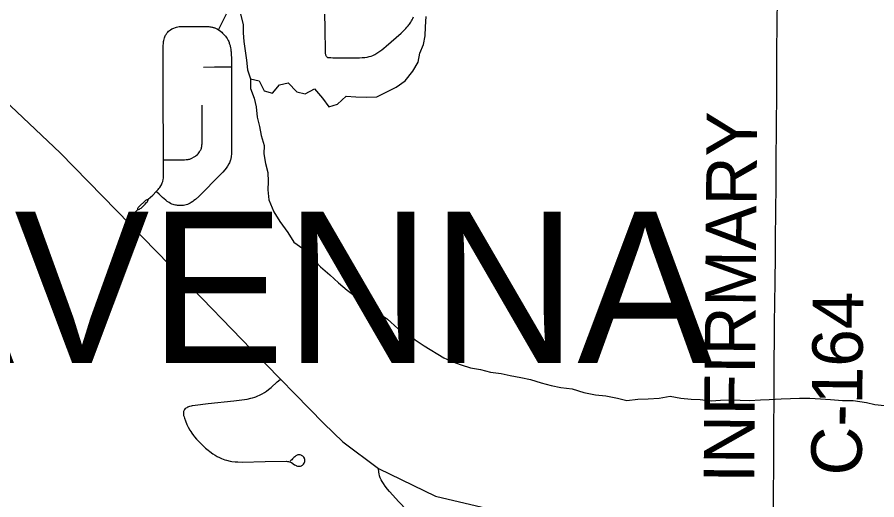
# Model space of a CAD drawing. Extents: x 0 to 34, y 0 to 22.
# Drawn here: x 6.114 to 7.081, y 15.953 to 16.497 of the extents above; entities that cross this region are included whole.
import ezdxf

# ---------------------------------------------------------------- set-up
doc = ezdxf.new("R2010")
doc.units = 0
for name, color, linetype in [('GM_X_County_Road', 7, 'Continuous'), ('GM_X_County_Road_Text', 7, 'Continuous'), ('GM_X_Minor_River', 7, 'Continuous'), ('GM_X_Township_Road', 7, 'Continuous'), ('GM_X_Township_Text', 7, 'Continuous'), ('SH_Text', 7, 'Continuous')]:
    doc.layers.add(name, color=color, linetype=linetype)

msp = doc.modelspace()

# ---------------------------------------------------------------- linework, layer by layer
at = {"layer": 'GM_X_County_Road'}
for points in [[(6.96457, 15.94259), (6.96493, 16.00864), (6.96526, 16.09208), (6.96585, 16.15178), (6.96662, 16.19817), (6.96685, 16.22811), (6.96676, 16.24735), (6.96754, 16.30754), (6.96784, 16.32982), (6.96821, 16.3767), (6.96833, 16.40802), (6.96848, 16.45844), (6.96872, 16.4883), (6.96914, 16.51872)], [(6.61999, 15.87248), (6.60999, 15.88265), (6.59119, 15.90161), (6.57606, 15.91717), (6.56178, 15.93189), (6.54315, 15.95108), (6.5327, 15.96251), (6.53052, 15.96512), (6.52794, 15.9685), (6.52592, 15.97148), (6.52447, 15.97373), (6.5233, 15.97579), (6.5223, 15.97804), (6.52149, 15.9804), (6.521, 15.98243), (6.52067, 15.98451), (6.52045, 15.98844)]]:
    msp.add_lwpolyline(points, dxfattribs=at)
at = {"layer": 'GM_X_Minor_River'}
for points in [[(6.36528, 16.49984), (6.36802, 16.48849), (6.3681, 16.47901), (6.36893, 16.46916), (6.37053, 16.45856), (6.37175, 16.44833), (6.37297, 16.43734), (6.37646, 16.42713), (6.37655, 16.41614), (6.38042, 16.40555), (6.38276, 16.39571), (6.38399, 16.38397), (6.38635, 16.37337), (6.38832, 16.36353), (6.39182, 16.35218), (6.39151, 16.3427), (6.39311, 16.33172), (6.39584, 16.32188), (6.3963, 16.31165), (6.396, 16.30217), (6.39685, 16.2908), (6.40263, 16.27757), (6.40953, 16.26663), (6.41833, 16.25419), (6.42523, 16.24325), (6.43513, 16.23612), (6.44467, 16.22671), (6.45497, 16.21542), (6.46564, 16.2064), (6.47556, 16.19738), (6.48508, 16.18911), (6.49689, 16.18048), (6.50754, 16.17298), (6.51897, 16.16434), (6.53038, 16.15647), (6.5422, 16.14632), (6.55169, 16.14185)], [(6.37646, 16.42713), (6.38632, 16.42494), (6.39171, 16.4136), (6.40119, 16.41102), (6.40906, 16.42056), (6.41889, 16.42253), (6.42843, 16.41237), (6.43791, 16.41016), (6.44846, 16.41593), (6.45725, 16.40538), (6.46452, 16.39558), (6.47433, 16.39869), (6.4841, 16.40749), (6.49471, 16.40681), (6.50644, 16.40652), (6.51855, 16.40699), (6.52911, 16.412), (6.54042, 16.41777), (6.5502, 16.42505), (6.55882, 16.43574), (6.56517, 16.44602), (6.56698, 16.45589), (6.57107, 16.46578), (6.57288, 16.47565), (6.57318, 16.48589), (6.57384, 16.49727)], [(6.55169, 16.14185), (6.5616, 16.1332), (6.57188, 16.12646), (6.59393, 16.11298), (6.60381, 16.1085), (6.6133, 16.10516), (6.62392, 16.10183), (6.63529, 16.10002), (6.64629, 16.09708), (6.65841, 16.09565), (6.66865, 16.09308), (6.6804, 16.09089), (6.6914, 16.0887), (6.70354, 16.085), (6.71454, 16.08206), (6.72553, 16.07986), (6.73804, 16.07806), (6.75131, 16.074), (6.76458, 16.07144), (6.77594, 16.07039), (6.78921, 16.06784), (6.79983, 16.06527), (6.81193, 16.0665), (6.82366, 16.06697), (6.83614, 16.06782), (6.84862, 16.06981), (6.86037, 16.06763), (6.87211, 16.06658), (6.88233, 16.06628), (6.89445, 16.06486), (6.90505, 16.06532), (6.9164, 16.06578), (6.92738, 16.06549), (6.9376, 16.06519), (6.95008, 16.06566), (6.95992, 16.06612), (6.97316, 16.06698), (6.98375, 16.06744), (6.99397, 16.06789), (7.00571, 16.06761), (7.01744, 16.06694), (7.0288, 16.06627), (7.04244, 16.06523), (7.05417, 16.06495), (7.06933, 16.06279), (7.07881, 16.06058), (7.08941, 16.05953)]]:
    msp.add_lwpolyline(points, dxfattribs=at)
at = {"layer": 'GM_X_Township_Road'}
for points in [[(6.3404, 16.48247), (6.34926, 16.50034)], [(6.46194, 16.45228), (6.46153, 16.4529), (6.46118, 16.45363), (6.46099, 16.45439), (6.46088, 16.4552), (6.46084, 16.45586), (6.46082, 16.45664), (6.46028, 16.48453), (6.46018, 16.5001)], [(6.46194, 16.45228), (6.46253, 16.45169), (6.46317, 16.45133), (6.46415, 16.45112), (6.46498, 16.45105), (6.46571, 16.45102), (6.46661, 16.451), (6.46891, 16.45098), (6.48159, 16.45095), (6.49903, 16.45098), (6.50193, 16.45112), (6.50516, 16.45136), (6.50766, 16.45171), (6.51002, 16.45222), (6.51209, 16.45287), (6.51398, 16.45359), (6.51609, 16.45458), (6.51846, 16.45594), (6.5209, 16.45756), (6.52401, 16.45985), (6.52633, 16.46175), (6.5289, 16.46393), (6.54598, 16.4787), (6.54858, 16.48114), (6.55113, 16.48371), (6.55244, 16.4852), (6.55378, 16.48684), (6.55456, 16.48783), (6.55523, 16.48875), (6.55595, 16.48981), (6.55678, 16.49108), (6.55757, 16.49233), (6.55824, 16.49346), (6.55914, 16.49521), (6.55992, 16.49695)], [(6.27868, 16.33595), (6.27854, 16.35987), (6.27831, 16.39346), (6.27823, 16.44757), (6.27824, 16.46239), (6.27831, 16.46513), (6.27839, 16.46652), (6.27845, 16.46771), (6.27861, 16.46903), (6.27882, 16.47037), (6.27917, 16.47198), (6.27958, 16.47332), (6.28007, 16.47462), (6.28089, 16.47631), (6.28137, 16.4771), (6.28188, 16.47785), (6.28229, 16.47844), (6.28289, 16.47919), (6.28345, 16.47984), (6.28429, 16.48066), (6.28523, 16.48148), (6.28652, 16.48244), (6.28794, 16.48327), (6.29021, 16.48437), (6.29198, 16.48505), (6.29325, 16.48543), (6.29448, 16.48568), (6.29617, 16.48591), (6.29746, 16.48603), (6.2993, 16.4861), (6.30053, 16.4861), (6.30351, 16.48614), (6.31083, 16.48626), (6.31918, 16.48624), (6.32435, 16.4862), (6.32724, 16.48611), (6.32939, 16.48598), (6.3305, 16.48586), (6.33175, 16.48569), (6.33277, 16.4855), (6.33349, 16.48532), (6.33432, 16.48509), (6.33518, 16.48484), (6.33583, 16.48463), (6.33645, 16.48441), (6.33786, 16.48384), (6.33894, 16.48333), (6.3404, 16.48247)], [(6.3404, 16.48247), (6.34123, 16.48192), (6.34283, 16.48069), (6.34402, 16.47968), (6.34509, 16.47872), (6.34619, 16.4776), (6.34685, 16.47688), (6.34772, 16.47586), (6.34819, 16.47528), (6.34911, 16.47403), (6.34999, 16.47268), (6.35092, 16.47112), (6.35136, 16.47024), (6.35186, 16.46912), (6.35223, 16.46817), (6.35259, 16.46723), (6.35293, 16.46625), (6.35338, 16.46467), (6.35358, 16.46383), (6.3539, 16.46225), (6.35416, 16.46073), (6.35426, 16.46002), (6.3544, 16.45878), (6.35451, 16.45748), (6.35471, 16.4543), (6.35486, 16.45082), (6.35495, 16.44753), (6.35508, 16.4407)], [(6.35508, 16.4407), (6.35513, 16.43043), (6.35509, 16.38575), (6.35519, 16.36524), (6.35521, 16.35608), (6.35513, 16.34868), (6.35505, 16.34487), (6.35499, 16.34308), (6.35492, 16.34193), (6.35479, 16.34048), (6.35456, 16.33869), (6.35437, 16.33778), (6.35413, 16.33673), (6.35389, 16.33583), (6.35353, 16.3347), (6.35274, 16.33267), (6.35221, 16.33159), (6.35056, 16.32877), (6.34896, 16.32647), (6.3476, 16.32473), (6.34519, 16.32201), (6.34304, 16.31973), (6.31823, 16.29488), (6.31458, 16.29153), (6.31284, 16.29007), (6.31141, 16.28901), (6.30977, 16.28789), (6.30858, 16.28718), (6.30702, 16.28639), (6.30554, 16.28579), (6.30414, 16.28536), (6.30119, 16.28466), (6.29883, 16.28448), (6.29694, 16.28448), (6.29577, 16.28457), (6.29433, 16.28474), (6.29303, 16.28492), (6.29217, 16.28507), (6.29061, 16.28541), (6.2895, 16.28573), (6.28797, 16.28626), (6.28652, 16.28692), (6.28478, 16.28786), (6.28274, 16.28922), (6.28103, 16.2905), (6.27736, 16.29369), (6.27351, 16.29728), (6.27079, 16.29982)], [(6.32343, 16.44031), (6.33597, 16.44056), (6.35095, 16.44067), (6.35508, 16.4407)], [(6.27868, 16.33595), (6.28343, 16.336), (6.30228, 16.33618), (6.30392, 16.33624), (6.30499, 16.33634), (6.30626, 16.3365), (6.30692, 16.33663), (6.30803, 16.3369), (6.3091, 16.33724), (6.31058, 16.33787), (6.31312, 16.33921), (6.31442, 16.34005), (6.31535, 16.34074), (6.31669, 16.3419), (6.31763, 16.34287), (6.31838, 16.34379), (6.31918, 16.34492), (6.31997, 16.34635), (6.32036, 16.34715), (6.32073, 16.34811), (6.32111, 16.34928), (6.32129, 16.34996), (6.32153, 16.35103), (6.32169, 16.35195), (6.32182, 16.35289), (6.32192, 16.35414), (6.32201, 16.35533), (6.32207, 16.35685), (6.3221, 16.35796), (6.32211, 16.35967), (6.32212, 16.36268), (6.32195, 16.37404), (6.32196, 16.39753)], [(6.27029, 16.30028), (6.27084, 16.30084), (6.27237, 16.3025), (6.2734, 16.30372), (6.27442, 16.30501), (6.27562, 16.3068), (6.27632, 16.30803), (6.27721, 16.31011), (6.27776, 16.31177), (6.27826, 16.31394), (6.27847, 16.31534), (6.27864, 16.31791), (6.27872, 16.32627), (6.27868, 16.33595)], [(6.2494, 16.2799), (6.25028, 16.28006), (6.25158, 16.28053), (6.25245, 16.28103), (6.25332, 16.28172), (6.25777, 16.28606), (6.25956, 16.28796), (6.26004, 16.28846), (6.26052, 16.28909), (6.261, 16.28999), (6.26121, 16.29086), (6.26125, 16.29156), (6.26636, 16.29638), (6.27029, 16.30028)], [(6.2494, 16.2799), (6.2495, 16.28057), (6.24965, 16.28118), (6.25014, 16.2822), (6.25069, 16.28294), (6.25821, 16.29034), (6.25878, 16.29078), (6.25933, 16.29111), (6.26011, 16.29141), (6.26125, 16.29156)], [(6.23691, 16.26745), (6.23928, 16.26982), (6.2494, 16.2799)], [(6.30173, 16.05407), (6.30249, 16.05512), (6.30328, 16.05597), (6.30404, 16.05666), (6.30503, 16.05735), (6.3058, 16.05778), (6.30636, 16.05807), (6.3071, 16.05838), (6.30833, 16.05875), (6.3102, 16.05923), (6.31125, 16.05945), (6.31401, 16.05986), (6.32862, 16.06157), (6.35765, 16.06472), (6.37257, 16.06675), (6.37662, 16.06755), (6.37883, 16.06809), (6.38112, 16.06882), (6.38252, 16.06936), (6.38464, 16.07025), (6.38669, 16.07117), (6.38942, 16.07262), (6.39208, 16.07422), (6.39431, 16.07572), (6.3967, 16.07754), (6.39951, 16.07988), (6.40636, 16.08592), (6.40969, 16.08885)], [(6.30173, 16.05407), (6.30142, 16.05341), (6.30113, 16.05261), (6.30091, 16.05156), (6.30086, 16.05039), (6.30099, 16.04909), (6.30119, 16.04817), (6.30161, 16.04673), (6.30209, 16.04524), (6.3033, 16.04209), (6.3049, 16.03822), (6.3063, 16.03523), (6.30811, 16.03188), (6.30922, 16.03011), (6.31051, 16.02819), (6.31232, 16.0257), (6.3134, 16.02431), (6.31581, 16.02149), (6.31765, 16.01954), (6.32335, 16.01391), (6.32595, 16.01149), (6.32871, 16.00907), (6.3307, 16.00751), (6.33422, 16.00502), (6.33669, 16.00346), (6.33873, 16.00223), (6.34135, 16.00091), (6.34377, 15.99985), (6.34752, 15.99849), (6.34954, 15.99787), (6.35359, 15.99693), (6.35552, 15.99658), (6.35909, 15.99613), (6.36205, 15.99592), (6.36685, 15.99584), (6.39303, 15.99635), (6.41676, 15.99665), (6.41798, 15.99658), (6.41932, 15.99643), (6.42042, 15.99617), (6.42147, 15.99577), (6.42252, 15.99517), (6.42603, 15.99272), (6.42687, 15.9922), (6.4276, 15.99179), (6.42823, 15.99153), (6.4291, 15.99125), (6.43012, 15.99105), (6.43074, 15.99099), (6.43189, 15.99106), (6.43255, 15.9912), (6.43373, 15.99159), (6.4343, 15.9919), (6.43499, 15.99239), (6.43563, 15.99297), (6.43603, 15.99348), (6.43672, 15.99456), (6.43704, 15.99531), (6.43735, 15.99638), (6.43748, 15.99722), (6.43748, 15.99801), (6.43743, 15.99881), (6.43722, 15.99965), (6.43697, 16.00029), (6.43645, 16.00117), (6.43572, 16.00198), (6.43517, 16.0025), (6.43456, 16.00295), (6.43392, 16.00333), (6.43324, 16.00359), (6.4322, 16.00386), (6.43153, 16.00394), (6.43055, 16.00395), (6.42965, 16.00377), (6.42879, 16.00344), (6.42813, 16.00313), (6.42752, 16.00277), (6.42685, 16.0023), (6.42627, 16.00183), (6.42526, 16.00088), (6.42379, 15.99942), (6.42291, 15.99846), (6.42185, 15.99745), (6.42095, 15.9967)]]:
    msp.add_lwpolyline(points, dxfattribs=at)
at = {"layer": 'SH_Text'}
msp.add_lwpolyline([(6.04363, 16.45614), (6.16219, 16.3439), (6.22585, 16.27897), (6.29975, 16.20287), (6.37745, 16.12252), (6.45878, 16.03908), (6.4804, 16.01858), (6.52045, 15.98844), (6.58451, 15.95751), (6.64988, 15.94219), (6.71462, 15.93934), (6.79663, 15.94028), (7.82198, 15.947)], dxfattribs=at)

# ---------------------------------------------------------------- texts
at = {"layer": 'GM_X_County_Road_Text'}
for s, rotation, p in [('INFIRMARY', 89.51393, (6.9429, 15.97219)), ('C-164', 89.45718, (7.06377, 15.98051))]:
    msp.add_text(s, height=0.056818, rotation=rotation, dxfattribs=at).set_placement(p)
at = {"layer": 'GM_X_Township_Text'}
msp.add_text('RAVENNA', height=0.170455, rotation=0.00001, dxfattribs=at).set_placement((5.7941, 16.10733))

doc.saveas('drawing.dxf')
